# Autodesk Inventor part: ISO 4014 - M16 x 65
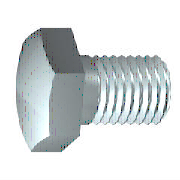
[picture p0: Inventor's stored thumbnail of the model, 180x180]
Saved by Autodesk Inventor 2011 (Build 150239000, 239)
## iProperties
Created: 2009-02
Part Number: ISO 4014 - M16 x 65
Material: Stainless Steel, 440C
Description: Hexagon head bolt - product grades A and B
Document SubType Name: Modeling
Standard: ISO 4014
Designer: V.de Jong
Standard Revision: Third edition 1999-09-01
Standards Organization: ISO
Language: en-US
Size Designation: M16 x 65
Categories: <MemberInstance><Categories><Category DisplayName="Fasteners" InternalName="e4da775c-781d-43d5-af7c-5136215cf5a6" Mnemonic="FSTN"><Category DisplayName="Bolts"
Density: 7.75 g/cm^3
Mass: 138.92 g
Surface Area: 50.2486 cm^2
Volume: 17.9252 cm^3
IsCustomPart: 0
Author: V.de Jong
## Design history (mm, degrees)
body "Solid1"
workplane "Work Plane1"
revolve "Body" stored, may be unused: angle "d12" = 90 deg
sketch "Sketch2"
  geometry: L1 (0, 13.856)-(12, 6.928); L2 (12, 6.928)-(12, -6.928); L3 (12, -6.928)-(0, -13.856); L4 (0, -13.856)-(-12, -6.928); L5 (-12, -6.928)-(-12, 6.928); L6 (-12, 6.928)-(0, 13.856); 2 further points
  constraints: 12 end point, 1 coincident, 1 vertical, 11 other
  dimensions: "d11" = 24 distance between parallel lines of L5 L2 (= SW)
extrude "Head" join sketch "Sketch2" distance "d3" = 9.2 (= KOH - SD); taper "d4" = 0 deg
revolve "Chamfer1" stored, may be unused: angle "d21" = 90 deg
feature "Thread" dims "d15" = 38 (= GEL), "d16" = 0
chamfer "Chamfer2" distance "d6" = 1.2269 (= -0.5 x SPD + 0.5 x GD); stored, may be unused: second distance "d7" = 1.227 (computed from GUL), angle "d55" = 45 deg
sketch "Sketch1"
  geometry: L1 (0, 11.245)-(0, 8); L2 (27, 8)-(65, 8); L3 (65, 8)-(65, 0); L4 (65, 0)-(-0.8, 0); L5 (-13.96, 0)-(78.16, 0) reference; L6 (-0.8, 0)-(-0.8, 11.245); L7 (-0.8, 11.245)-(0, 11.245); L8 (27, 8)-(25.773, 8); L9 (25.773, 8)-(0, 8); L10 (0, -2.249)-(0, 13.494) reference
  constraints: 16 end point, 2 collinear, 2 perpendicular, 1 parallel
  dimensions: "d0" = 65 distance between parallel lines of L3 L1 (= NLG); "d1" = 38 distance from line of L2.start L3 (= GEL); "d2" = 16 diameter of L2 L4 (= GD); "d9" = 0.8001 distance between parallel lines of L6 L1 (computed from SD); "d10" = 22.49 diameter of L7 L4 (= SD2); "d13" = 1.227 distance of L2.start L8.end (computed from GAL); "d14" = 16 diameter of L9 L4 (= BDM)
sketch "Sketch4"
  geometry: L1 (-10, 12)-(-10, 13.856); L2 (-10, 13.856)-(-8.928, 13.856); L3 (-8.928, 13.856)-(-10, 12); L4 (-11.84, 0)-(1.04, 0) reference; L5 (-0.8, 13.856)-(-10, 13.856) reference; L6 (-10, 6.928)-(-10, 13.856) reference
  constraints: 6 end point, 2 collinear, 1 perpendicular, 1 vertical
  dimensions: "d5" = 30 deg angle of L3 L1 (= ANG1); "d19" = 24 diameter of L1.start L4 (= SW0)
other parameters: "NLG" = 65 [user parameter; used in 1 equation term], "GD" = 16 (= NND) [user parameter; used in 2 equation terms], "BDM" = 16 (= NND) [user parameter; used in 1 equation term], "KOH" = 10 [user parameter; used in 1 equation term], "GEL" = 38 [user parameter; used in 2 equation terms], "SW" = 24 [user parameter; used in 3 equation terms], "SW0" = 24 (= SW) [user parameter; used in 1 equation term], "SPD" = 13.5462 (= NND - 1.2269 x PTC) [user parameter; used in 1 equation term], "SD2" = 22.49 [user parameter; used in 2 equation terms], "SD" = 0.8 [user parameter; used in 2 equation terms], "ANG1" = 30 deg [user parameter; used in 1 equation term], "GAL" = 1.2269 (= 0.61345 x PTC) [user parameter; used in 1 equation term], "GUL" = 1.2269 (= 0.61345 x PTC) [user parameter; used in 1 equation term], "d8" = 0, "RR" = 0.6 [user parameter], "d57" = 0, "d58" = 0, "TPU" = 5 (computed from PTC) [user parameter], "GD1" = 13.5462 (= THREADDIA - 1.2269 x PTC) [user parameter], "THREADDIA" = 16 [user parameter; used in 1 equation term], "SDH" = 22.49 (= SD2) [user parameter], "TOA" = 30 deg [user parameter], "PTC" = 2 [user parameter; used in 5 equation terms], "NND" = 16 [user parameter; used in 3 equation terms], "E0" = 27.72 (= 1.155 x SW) [user parameter]
